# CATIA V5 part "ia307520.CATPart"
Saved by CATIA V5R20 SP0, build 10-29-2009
Part number: IA 307520
Revision: ANY
Definition: UNKNOWN
Nomenclature: IA 307520
Source: Unknown
Bounding box of the stored display mesh (mm): x -1.5 to 1.5, y -7.75 to 0, z -1.5 to 1.5
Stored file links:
  C:\Users\Utente\Desktop\IO LAVORO\3D X SITO CF\CUMSA\3D files IA\IA 307520\ia307520.CATPart
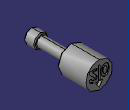
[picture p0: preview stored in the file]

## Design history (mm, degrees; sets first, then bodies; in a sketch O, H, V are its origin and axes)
Body1 "Cortar-Extruir2" (main body)
  Solid1: solid without history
